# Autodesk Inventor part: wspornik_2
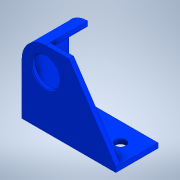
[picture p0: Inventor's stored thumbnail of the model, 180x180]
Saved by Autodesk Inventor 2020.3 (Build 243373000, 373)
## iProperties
Created: 2021-01
Part Number: wspornik_2
Material: Ogólny
Document SubType Name: Modeling
Designer: Dom
Density: 1 g/cm^3
Appearance: Domyślna
Author: Dom
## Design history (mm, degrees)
sketch "Szkic1"
  geometry: L1 (0, 0)-(100, 0); L2 (100, 0)-(100, 5); L3 (50, 80)-(25, 80); L4 (0, 55)-(0, 0); L5 (50, 80)-(100, 5); C1 r 15 at (25, 55); A1 r 25 centre (25, 55) between (25, 80) and (0, 55)
  constraints: 10 end point, 2 centre point, 2 parallel, 2 point on circle, 1 coincident, 1 horizontal, 1 perpendicular, 1 tangent
  dimensions: "d4" = 30 diameter of C1; "d5" = 25 distance from line of L4 C1.centre; "d6" = 55 distance from line of L1 C1.centre; "d7" = 5 distance of L2.end L1.end; "d8" = 50 diameter of A1
extrude "Wyciągnięcie proste1" new body sketch "Szkic1" distance "d9" = 5; taper "d10" = 0 deg
sketch "Szkic2"
  geometry: L1 (0, 55)-(0, 0) reference; L2 (100, 0)-(100, 5) reference; L3 (0, 0)-(100, 0); L4 (100, 0)-(100, 5); L5 (100, 5)-(0, 5); L6 (0, 5)-(0, 0); 2 further points
  constraints: 8 end point, 2 parallel, 1 horizontal, 1 perpendicular
extrude "Wyciągnięcie proste2" join sketch "Szkic2" distance "d11" = 45; taper "d12" = 0 deg
sketch "Szkic3"
  geometry: L1 (0, -5)-(0, -45) reference; C1 r 5.5 at (-20, -25); C2 r 5.5 at (-80, -25); 6 further points; 1 other entity
  constraints: 2 centre point, 2 horizontal alignment, 1 equal radius, 1 midpoint, 2 other
  dimensions: "d13" = 11 diameter of C1; "d18" = 20 distance from line of C1.centre L1; "d19" = 20 dimension on C2.centre (= d18)
extrude "Wyciągnięcie proste3" cut sketch "Szkic3" extent not by distance; stored distance "d15" = 60; taper "d16" = 0 deg
sketch "Szkic4"
  geometry: L1 (0, 55)-(0, 5) reference; L2 (-5, 5)-(-5, 55); L3 (0, 55)-(0, 5); L4 (-100, 5)-(0, 5) reference; L5 (-50, 80)-(-25, 80) reference; L6 (-25, 75)-(-25, 80); A1 r 25 centre (-25, 55) between (0, 55) and (-25, 80) reference; A2 r 20 centre (-25, 55) between (-5, 55) and (-25, 75); A3 r 25 centre (-25, 55) between (0, 55) and (-25, 80); 1 further point
  constraints: 6 end point, 4 point on circle, 2 centre point, 1 vertical, 2 other
  dimensions: "d20" = 5 distance between parallel lines of L1 L2; "d21" = 0 radial gap between concentric circles of A1 A3
extrude "Wyciągnięcie proste4" join sketch "Szkic4" distance "d22" = 40; taper "d23" = 0 deg
chamfer "Faza1" distance "d24" = 1; stored, may be unused: second distance "d25" = 2, angle "d26" = 45 deg
node "Bryła1"
